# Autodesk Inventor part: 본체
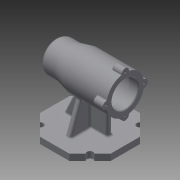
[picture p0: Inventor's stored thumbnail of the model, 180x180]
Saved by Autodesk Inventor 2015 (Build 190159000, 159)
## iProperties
Created: 2019-12
Part Number: 본체
Material: 일반
Document SubType Name: Modeling
Designer: now
Density: 1 g/cm^3
Appearance: 기본값
Author: now
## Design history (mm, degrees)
sketch "스케치1" dims "d0" = 112
  geometry: L1 (23.196, -56)-(-23.196, -56); L2 (-23.196, -56)-(-56, -23.196); L3 (-56, -23.196)-(-56, 23.196); L4 (-56, 23.196)-(-23.196, 56); L5 (-23.196, 56)-(23.196, 56); L6 (23.196, 56)-(56, 23.196); L7 (56, 23.196)-(56, -23.196); L8 (56, -23.196)-(23.196, -56); 4 further points
  constraints: 16 end point, 2 coincident, 1 midpoint, 1 vertical, 20 other
extrude "돌출1" new body sketch "스케치1" distance "d1" = 10; taper "d2" = 0 deg
sketch "스케치2"
  geometry: L1 (-56, -23.196)-(-23.196, -56) reference; L2 (0, 0)-(-67.03, -67.03); L3 (0, 0)-(0, -69.123); C1 r 5 at (-39.598, -39.598)
  constraints: 4 end point, 1 centre point, 1 midpoint, 1 point on line, 1 vertical
  dimensions: "d3" = 45 deg angle of L3 L2; "d4" = 10 diameter of C1
extrude "돌출2" cut sketch "스케치2" stored distance "d5" = 10; taper "d6" = 0 deg
sketch "스케치3"
  geometry: L1 (-56, 23.196)-(-56, -23.196) reference; L2 (-23.196, -56)-(23.196, -56) reference; L3 (56, -23.196)-(56, 23.196) reference; L4 (23.196, 56)-(-23.196, 56) reference; L5 (-38, -4)-(31, -4); L6 (31, -4)-(31, 4); L7 (31, 4)-(-38, 4); L8 (-38, 4)-(-38, -4); L9 (-4, -36)-(4, -36); L10 (4, -36)-(4, 36); L11 (4, 36)-(-4, 36); L12 (-4, 36)-(-4, -36); 1 further point
  constraints: 16 end point, 4 parallel, 2 horizontal, 2 perpendicular
  dimensions: "d10" = 4 distance from line of L5 point (0, 0); "d11" = 8 distance between parallel lines of L5 L7; "d12" = 4 distance from line of point (0, 0) L12; "d13" = 8 distance between parallel lines of L10 L12; "d14" = 20 distance between parallel lines of L2 L9; "d15" = 20 distance between parallel lines of L11 L4; "d16" = 25 distance between parallel lines of L3 L6; "d17" = 18 distance between parallel lines of L1 L8
extrude "돌출3" join sketch "스케치3" distance "d18" = 70; taper "d19" = 0 deg
feature "면 기울기1" dims angle "d20" = 20 deg
feature "면 기울기2" dims angle "d21" = 25 deg
sketch "스케치4"
  geometry: L1 (56, 0)-(-56, 0) reference; L2 (-56, 0)-(-56, 10) reference; L3 (-56, 10)-(-31, 10) reference; L4 (-31, 10)-(-31, 80) reference; L5 (-31, 80)-(5.358, 80) reference; L6 (5.358, 80)-(38, 10) reference; L7 (38, 10)-(56, 10) reference; L8 (56, 10)-(56, 0) reference; L9 (-56, 80)-(56, 80); L10 (56, 80)-(56, 105); L11 (11, 110)-(-56, 110); L12 (-56, 110)-(-56, 80); L13 (11, 110)-(31, 105); L14 (31, 105)-(56, 105); 1 further point
  constraints: 12 end point, 2 horizontal, 2 parallel, 1 collinear, 1 perpendicular
  dimensions: "d22" = 0 horizontal distance of L1.end L9.start; "d23" = 30 distance of L11.end L9.start; "d24" = 112 distance between parallel lines of L10 L12; "d25" = 67 distance of L11.start L11.end; "d26" = 25 distance of L13.end L10.end; "d27" = 25 distance between parallel lines of L9 L14
revolve "회전1" sketch "스케치4" stored, may be unused: angle "d28" = 90 deg
sketch "스케치5"
  geometry: C1 r 30 at (0, 0) reference; C2 r 21 at (0, 0); 1 further point
  constraints: 1 centre point, 1 coincident
  dimensions: "d29" = 42 diameter of C2
extrude "돌출4" cut sketch "스케치5" distance "d30" = 15; taper "d31" = 0 deg
sketch "스케치6"
  geometry: C1 r 21 at (0, 0) reference; C2 r 24 at (0, 0); 1 further point
  constraints: 1 centre point, 1 coincident
  dimensions: "d32" = 48 diameter of C2
extrude "돌출5" cut sketch "스케치6" distance "d33" = 54; taper "d34" = 0 deg
sketch "스케치7"
  geometry: C1 r 24 at (0, 0) reference; C2 r 21 at (0, 0); 1 further point
  constraints: 1 centre point, 1 coincident
  dimensions: "d35" = 42 diameter of C2
extrude "돌출6" cut sketch "스케치7" distance "d36" = 12; taper "d37" = 0 deg
sketch "스케치8"
  geometry: C1 r 21 at (0, 0) reference; C2 r 17.5 at (0, 0); 1 further point
  constraints: 1 centre point, 1 coincident
  dimensions: "d38" = 35 diameter of C2
extrude "돌출7" cut sketch "스케치8" distance "d39" = 18; taper "d40" = 0 deg
sketch "스케치9"
  geometry: C1 r 17.5 at (0, 0) reference; C2 r 16 at (0, 0); 1 further point
  constraints: 1 centre point, 1 coincident
  dimensions: "d41" = 32 diameter of C2
extrude "돌출8" cut sketch "스케치9" distance "d42" = 4; taper "d43" = 0 deg
sketch "스케치10"
  geometry: C1 r 16 at (0, 0) reference; C2 r 10.5 at (0, 0); 1 further point
  constraints: 1 centre point, 1 coincident
  dimensions: "d44" = 21 diameter of C2
extrude "돌출9" cut sketch "스케치10" distance "d45" = 3; taper "d46" = 0 deg
fillet "모깎기1" dims "d47" = 0.3
sketch "스케치11"
  geometry: C1 r 21 at (0, 0) reference; C2 r 6 at (-30, 0); 2 further points
  constraints: 1 centre point, 1 coincident, 1 horizontal alignment
  dimensions: "d49" = 30 distance of C1.centre point (-30, 0); "d50" = 6 radius of C2
extrude "돌출10" join sketch "스케치11" distance "d51" = 16; taper "d52" = 0 deg
fillet "모깎기3" dims "d53" = 3
fillet "모깎기4" dims "d54" = 1
fillet "모깎기5" dims "d55" = 3
sketch "스케치12"
  geometry: A1 r 6 centre (0, 0) between (-0.171, 5.998) and (-0.171, -5.998) reference; 1 further point
hole "구멍1" sketch "스케치12" at (0, 0) diameter "d56" = 3.242; stored, may be unused: countersink angle "d60" = 90 deg, drill point angle "d62" = 118 deg; dims "d57" = 8, "d58" = 4, "d59" = 2, "d61" = 11
fillet "모깎기6" dims "d66" = 3
fillet "모깎기7" dims "d67" = 3
fillet "모깎기8" dims "d68" = 10
fillet "모깎기9" dims "d69" = 3
fillet "모깎기10" dims "d70" = 3
chamfer "모따기1" distance "d71" = 1; stored, may be unused: second distance "d72" = 2, angle "d73" = 45 deg
node "솔리드1"
pattern_circular "원형 패턴1" dims angle "d8" = 360 deg
pattern_circular "원형 패턴2" dims "d64" = 360 deg
node "절단 모서리 투영1"
